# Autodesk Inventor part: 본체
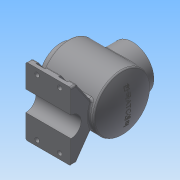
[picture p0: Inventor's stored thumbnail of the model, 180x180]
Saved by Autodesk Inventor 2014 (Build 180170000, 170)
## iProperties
Created: 2017-04
Part Number: 본체
Material: 일반
Document SubType Name: Modeling
Designer: 학생용
Density: 1 g/cm^3
Appearance: 기본값
Author: 학생용
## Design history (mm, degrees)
sketch "스케치1"
  geometry: L1 (-60, 0)-(60, 0); L2 (-60, 0)-(-60, 38); L3 (-60, 38)-(-48, 38); L4 (-48, 38)-(-48, 50); L5 (-48, 50)-(48.336, 50); L6 (-38, 40)-(41.916, 40); L7 (-38, 40)-(-38, 27); L8 (-38, 27)-(-60, 27); A1 r 113 centre (-53, 0) between (60, 0) and (48.336, 50); A2 r 103 centre (-53, 0) between (50, 0) and (41.916, 40); 2 further points
  constraints: 16 end point, 4 perpendicular, 4 point on circle, 3 parallel, 3 point on line, 2 centre point, 1 coincident, 1 horizontal, 1 midpoint
  dimensions: "d0" = 226 diameter of A1; "d1" = 10 radial gap between concentric circles of A1 A2; "d2" = 100 diameter of L5 L1; "d3" = 54 diameter of L8 L1; "d4" = 76 diameter of L3 L1; "d5" = 80 diameter of L6 L1; "d6" = 22 distance of L7.end L8.end; "d7" = 12 distance of L2.end L3.end; "d15" = 108 distance from line of L1.end L4
revolve "회전1" sketch "스케치1" stored, may be unused: angle "d9" = 90 deg
node "작업 평면1"
sketch "스케치2"
  geometry: L1 (-40, 50)-(40, 50); L2 (40, 50)-(40, -50); L3 (40, -50)-(-40, -50); L4 (-40, -50)-(-40, 50); L5 (48, 50)-(48, -50) reference; L6 (48, 50)-(48, -50) reference; L7 (-48.336, 50)-(-48.336, -50) reference; L8 (-48.336, 50)-(-48.336, -50) reference; L9 (60, 38)-(60, -38) reference; L10 (60, 38)-(60, -38) reference; L11 (48, 38)-(48, -38) reference; A1 r 113 centre (53, 0) between (-48.336, 50) and (-48.336, -50) reference; 2 further points
  constraints: 8 end point, 2 parallel, 1 horizontal, 1 horizontal alignment, 1 midpoint, 1 perpendicular
  dimensions: "d11" = 80 distance of L2.end L3.end; "d12" = 100 distance of L1.end L2.end; "d14" = 8 distance between parallel lines of L11 L2
  node "투영된 루프1"
  node "투영된 루프2"
node "작업 평면2"
sketch "스케치3"
  geometry: L1 (-21.584, -45.101)-(-60, -72); L2 (-60, -72)-(-60, -82); L3 (60, -82)-(60, -72); L4 (60, -72)-(21.584, -45.101); L5 (-60, -82)-(-18, -82); L6 (18, -82)-(60, -82); C1 r 27 at (0, 0) reference; A1 r 50 centre (0, 0) between (-21.584, -45.101) and (21.584, -45.101) reference; A2 r 18 centre (0, -82) between (18, -82) and (-18, -82); 2 further points
  constraints: 12 end point, 4 perpendicular, 4 point on circle, 2 horizontal alignment, 1 centre point, 1 coincident, 1 collinear, 1 vertical, 1 vertical alignment
  dimensions: "d17" = 55 deg angle of L3 L4; "d18" = 10 distance of L3.start L3.end; "d19" = 18 radius of A2; "d22" = 120 distance between parallel lines of L3 L2; "d27" = 82 distance from line of L6 point (0, 0); "d28" = 55 deg angle of L1 L3; "d29" = 42 distance from line of L6.start L3
extrude "돌출1" join sketch "스케치3" distance "d30" = 80; taper "d31" = 0 deg
node "작업 평면3"
sketch "스케치4"
  geometry: L1 (-80, 43.029)-(0, 43.029) reference; L2 (0, 43.029)-(0, 0) reference; L3 (0, 0)-(-80, 0) reference; L4 (-80, 0)-(-80, 43.029) reference; L5 (-80, 120)-(0, 120) reference; L6 (0, 120)-(0, 76.971) reference; L7 (0, 76.971)-(-80, 76.971) reference; L8 (-80, 76.971)-(-80, 120) reference; L9 (-68, 110)-(-68, 120); L10 (-52, 110)-(-52, 120); L11 (-28, 110)-(-28, 120); L12 (-12, 110)-(-12, 120); L13 (-28, 10)-(-28, 0); L14 (-12, 10)-(-12, 0); L15 (-52, 10)-(-52, 0); L16 (-68, 10)-(-68, 0); A1 r 8 centre (-60, 110) between (-68, 110) and (-52, 110); A2 r 8 centre (-20, 110) between (-28, 110) and (-12, 110); A3 r 8 centre (-60, 10) between (-52, 10) and (-68, 10); A4 r 8 centre (-20, 10) between (-28, 10) and (-12, 10); 1 further point
  constraints: 16 end point, 8 point on circle, 8 point on line, 8 tangent, 6 parallel, 4 centre point, 3 equal radius, 2 horizontal alignment, 2 perpendicular, 2 vertical alignment
  dimensions: "d33" = 16 diameter of A1; "d34" = 10 distance from line of L5 A1.centre; "d35" = 20 distance from line of L8 A1.centre; "d37" = 40 distance of A4.centre A3.centre; "d38" = 10 distance from line of L3 A3.centre
extrude "돌출2" cut sketch "스케치4" distance "d39" = 40; taper "d40" = 0 deg
hole "구멍1" diameter "d43" = 8; stored, may be unused: countersink angle "d47" = 90 deg, drill point angle "d49" = 118 deg; dims "d44" = 6, "d45" = 4, "d46" = 2, "d48" = 8, "d56" = 10, "d57" = 10
fillet "모깎기1" dims "d58" = 3
fillet "모깎기2" dims "d59" = 3
fillet "모깎기3" dims "d60" = 3
chamfer "모따기1" distance "d61" = 1; stored, may be unused: second distance "d62" = 2, angle "d63" = 45 deg
node "작업 평면4"
sketch "스케치5"
  geometry: L1 (20, 56)-(20, -20) reference; C1 r 38 at (-42, 18); 1 further point
  constraints: 1 centre point, 1 horizontal alignment, 1 midpoint
  dimensions: "d65" = 62 distance from line of L1 C1.centre; "d67" = 76 diameter of C1
extrude "돌출3" join sketch "스케치5" stored distance "d68" = 40; taper "d69" = 0 deg
sketch "스케치6"
  geometry: C1 r 38 at (0, 0) reference; C2 r 27 at (0, 0); 1 further point
  constraints: 1 centre point, 1 coincident
  dimensions: "d70" = 54 diameter of C2
extrude "돌출4" cut sketch "스케치6" distance "d71" = 40; taper "d72" = 0 deg
sketch "스케치7"
  geometry: C1 r 38 at (0, 0) reference; 1 further point
  constraints: 1 vertical alignment
  dimensions: "d73" = 32.5 distance of C1.centre point (0, 32.5)
hole "구멍2" sketch "스케치7" at (0, 32.5) diameter "d74" = 3.242; stored, may be unused: countersink angle "d78" = 90 deg, drill point angle "d80" = 118 deg; dims "d75" = 8, "d76" = 4, "d77" = 2, "d79" = 10
sketch "스케치8"
  geometry: C1 r 27 at (0, 0) reference; 2 further points
  constraints: 1 vertical alignment
  dimensions: "d84" = 32.5 distance of C1.centre point (0, 32.5)
hole "구멍3" sketch "스케치8" at (0, 32.5) diameter "d85" = 3.242; stored, may be unused: countersink angle "d89" = 90 deg, drill point angle "d91" = 118 deg; dims "d86" = 8, "d87" = 4, "d88" = 2, "d90" = 10
node "작업 평면5"
sketch "스케치9"
  geometry: C1 r 48.282 at (0, 0) reference; 2 further points
  constraints: 1 coincident, 1 other
feature "엠보싱1" sketch "스케치9" dims "d0" = 226, "d1" = 10, "d2" = 100, "d3" = 54, "d4" = 76, "d5" = 80, "d6" = 22, "d7" = 12, "d15" = 108, "d96" = 0.5, "d97" = 0
fillet "모깎기4" dims "d98" = 3
chamfer "모따기2" distance "d99" = 1; stored, may be unused: second distance "d100" = 2, angle "d101" = 45 deg
node "솔리드1"
pattern_linear "직사각형 패턴1" dims "d52" = 40
pattern_circular "원형 패턴1" dims angle "d82" = 360 deg
pattern_circular "원형 패턴2" dims angle "d93" = 360 deg
node "절단 모서리 투영1"
node "절단 모서리 투영2"
other parameters: "d10" = -82, "d16" = -8, "d21" = 82, "d32" = -6, "d64" = -147
